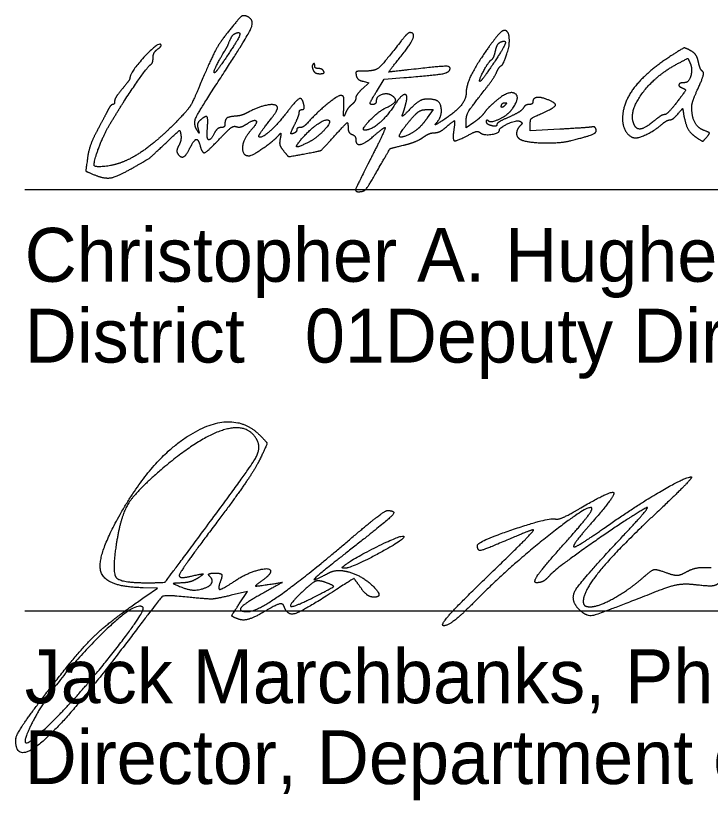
# Model space of a CAD drawing. Extents: x 0 to 64.8, y -5 to 22.
# Drawn here: x 24.504 to 26.31, y 6.793 to 8.831 of the extents above; entities that cross this region are included whole.
import ezdxf

# ---------------------------------------------------------------- set-up
doc = ezdxf.new("R2010")
doc.units = 0
doc.layers.add('SH_Data', color=7, linetype='Continuous')
doc.layers.add('SH_Text', color=7, linetype='Continuous')

msp = doc.modelspace()

# ---------------------------------------------------------------- linework, layer by layer
at = {"layer": 'SH_Data'}
for p, q in [((24.5279, 8.3799), (28.0279, 8.3799)), ((24.5279, 7.2848), (28.0279, 7.2848))]:
    msp.add_line(p, q, dxfattribs=at)
at = {"layer": 'SH_Text'}
for p, q in [((26.2707, 8.5169), (26.2707, 8.5169)), ((24.9902, 7.4899), (24.9902, 7.4899)), ((25.3555, 7.4), (25.3555, 7.4)), ((25.7273, 7.371), (25.7273, 7.371)), ((25.3107, 7.3583), (25.3107, 7.3583))]:
    msp.add_line(p, q, dxfattribs=at)
for points in [[(25.4419, 8.6333), (25.4621, 8.6661), (25.5135, 8.6703)], [(25.4072, 8.6608), (25.4226, 8.6571), (25.4054, 8.641)], [(25.5725, 8.5872), (25.5892, 8.5872), (25.574, 8.5655)], [(25.6948, 8.5538), (25.6749, 8.5396), (25.675, 8.5551)], [(25.9184, 8.5362), (25.8416, 8.5318), (25.8416, 8.548)], [(24.8425, 7.3229), (24.8732, 7.3441), (24.8354, 7.3448)], [(25.0855, 7.3031), (25.1067, 7.3354), (25.0649, 7.3253)]]:
    msp.add_lwpolyline(points, dxfattribs=at)
for points in [[(25.0246, 8.6505), (25.1054, 8.7743), (25.1264, 8.8214), (25.1044, 8.8298)], [(25.1044, 8.8298), (25.0968, 8.8327), (25.0867, 8.8266), (25.0767, 8.8135)], [(25.0767, 8.8135), (25.0455, 8.7767), (25.0161, 8.7299), (24.9843, 8.6531)], [(25.0757, 8.7854), (25.0908, 8.7913), (25.0811, 8.7664), (25.0503, 8.721)], [(25.5291, 8.7872), (25.5258, 8.7872), (25.5156, 8.7774), (25.5063, 8.7655)], [(25.5143, 8.7364), (25.534, 8.7612), (25.5416, 8.7872), (25.5291, 8.7872)], [(25.7797, 8.7917), (25.7739, 8.7953), (25.7594, 8.7834), (25.75, 8.7706)], [(25.7863, 8.7492), (25.7883, 8.7642), (25.7857, 8.788), (25.7797, 8.7917)], [(25.0574, 8.7583), (25.0637, 8.7729), (25.0702, 8.7833), (25.0757, 8.7854)], [(25.75, 8.7706), (25.7275, 8.7428), (25.6751, 8.6581), (25.675, 8.6289)], [(24.8816, 8.7561), (24.8747, 8.763), (24.8021, 8.6844), (24.8013, 8.6692)], [(24.8733, 8.7442), (24.8797, 8.7489), (24.8834, 8.7542), (24.8816, 8.7561)], [(25.0481, 8.74), (25.052, 8.7469), (25.0562, 8.7536), (25.0574, 8.7583)], [(25.5063, 8.7655), (25.4587, 8.7043), (25.4382, 8.6872), (25.4124, 8.6872)], [(25.7658, 8.7632), (25.781, 8.7691), (25.7712, 8.7442), (25.7404, 8.6988)], [(25.7515, 8.74), (25.7538, 8.7507), (25.7603, 8.7611), (25.7658, 8.7632)], [(25.7566, 8.6888), (25.761, 8.6989), (25.7732, 8.7043), (25.7863, 8.7492)], [(26.2583, 8.7405), (26.2441, 8.7481), (26.2388, 8.7468), (26.2103, 8.7285)], [(24.8616, 8.7218), (24.8616, 8.7295), (24.8669, 8.7395), (24.8733, 8.7442)], [(25.0211, 8.6827), (25.0163, 8.6827), (25.0437, 8.7345), (25.0481, 8.74)], [(25.5258, 8.6905), (25.4738, 8.6845), (25.4736, 8.6853), (25.5143, 8.7364)], [(25.741, 8.7168), (25.7444, 8.7189), (25.7492, 8.7294), (25.7515, 8.74)], [(26.2103, 8.7285), (26.1449, 8.6865), (26.0816, 8.6051), (26.0816, 8.5631)], [(26.2788, 8.7112), (26.2762, 8.7232), (26.2676, 8.7355), (26.2583, 8.7405)], [(24.8548, 8.7038), (24.8585, 8.7061), (24.8616, 8.7142), (24.8616, 8.7218)], [(25.0503, 8.721), (25.036, 8.7), (25.0229, 8.6827), (25.0211, 8.6827)], [(25.2775, 8.7052), (25.2752, 8.703), (25.2751, 8.6965), (25.2772, 8.6908)], [(25.2816, 8.7016), (25.2816, 8.7059), (25.2797, 8.7075), (25.2775, 8.7052)], [(25.7112, 8.6605), (25.7064, 8.6605), (25.7338, 8.7124), (25.741, 8.7168)], [(26.1106, 8.5508), (26.0984, 8.5825), (26.1671, 8.6761), (26.2249, 8.7066)], [(26.2249, 8.7066), (26.2511, 8.7204), (26.2517, 8.7204), (26.2574, 8.7078)], [(26.2574, 8.7078), (26.264, 8.693), (26.2541, 8.6572), (26.2433, 8.6572)], [(26.2897, 8.6864), (26.2862, 8.6887), (26.2813, 8.6998), (26.2788, 8.7112)], [(24.7484, 8.5475), (24.7777, 8.5971), (24.847, 8.6989), (24.8548, 8.7038)], [(25.2772, 8.6908), (25.2794, 8.6851), (25.2875, 8.6805), (25.2951, 8.6805)], [(25.2912, 8.6938), (25.2859, 8.6938), (25.2816, 8.6973), (25.2816, 8.7016)], [(25.3049, 8.6872), (25.3027, 8.6908), (25.2965, 8.6938), (25.2912, 8.6938)], [(25.2951, 8.6805), (25.3028, 8.6805), (25.3072, 8.6835), (25.3049, 8.6872)], [(25.4124, 8.6872), (25.3923, 8.6872), (25.3877, 8.6849), (25.3895, 8.6758)], [(25.5135, 8.6703), (25.5954, 8.6771), (25.6303, 8.6833), (25.6331, 8.6916)], [(25.6331, 8.6916), (25.6359, 8.7001), (25.6065, 8.6997), (25.5258, 8.6905)], [(25.7404, 8.6988), (25.7261, 8.6778), (25.713, 8.6605), (25.7112, 8.6605)], [(25.7251, 8.6405), (25.7381, 8.657), (25.7523, 8.6788), (25.7566, 8.6888)], [(26.2789, 8.6445), (26.289, 8.6667), (26.2935, 8.684), (26.2897, 8.6864)], [(24.8013, 8.6692), (24.8012, 8.6663), (24.7922, 8.6535), (24.7813, 8.6408)], [(25.3895, 8.6758), (25.3907, 8.6696), (25.3986, 8.6628), (25.4072, 8.6608)], [(24.9843, 8.6531), (24.9656, 8.608), (24.9515, 8.5859), (24.9232, 8.5568)], [(24.9753, 8.5348), (24.966, 8.5495), (24.98, 8.5822), (25.0246, 8.6505)], [(26.2433, 8.6572), (26.2303, 8.6572), (26.2261, 8.6476), (26.2373, 8.6433)], [(26.2616, 8.5946), (26.2616, 8.6013), (26.2694, 8.6238), (26.2789, 8.6445)], [(24.7813, 8.6408), (24.7705, 8.6281), (24.7616, 8.6138), (24.7616, 8.6091)], [(25.3495, 8.6238), (25.3413, 8.6238), (25.2862, 8.5785), (25.2625, 8.5522)], [(25.3572, 8.5938), (25.3579, 8.6148), (25.3556, 8.6238), (25.3495, 8.6238)], [(25.4054, 8.641), (25.396, 8.6321), (25.3883, 8.6212), (25.3883, 8.6168)], [(25.4317, 8.6005), (25.4243, 8.6005), (25.4268, 8.6088), (25.4419, 8.6333)], [(25.4812, 8.6241), (25.47, 8.631), (25.4416, 8.6212), (25.4416, 8.6104)], [(25.4658, 8.5914), (25.4882, 8.602), (25.4947, 8.6158), (25.4812, 8.6241)], [(25.519, 8.6045), (25.5247, 8.6271), (25.5065, 8.6256), (25.4912, 8.6022)], [(25.675, 8.6289), (25.6749, 8.6126), (25.6435, 8.5771), (25.6116, 8.5573)], [(25.675, 8.5551), (25.675, 8.5715), (25.6872, 8.5923), (25.7251, 8.6405)], [(25.7924, 8.5856), (25.8179, 8.6192), (25.787, 8.6385), (25.7531, 8.6101)], [(26.2373, 8.6433), (26.2464, 8.6398), (26.2442, 8.634), (26.2232, 8.6068)], [(24.7616, 8.6091), (24.7616, 8.6044), (24.7594, 8.6005), (24.7566, 8.6005)], [(25.2537, 8.5988), (25.2498, 8.619), (25.233, 8.6117), (25.2083, 8.5789)], [(25.3883, 8.6168), (25.3883, 8.6124), (25.3834, 8.6048), (25.3775, 8.5999)], [(25.4416, 8.6104), (25.4416, 8.605), (25.4371, 8.6005), (25.4317, 8.6005)], [(25.5105, 8.5761), (25.513, 8.5829), (25.5168, 8.5956), (25.519, 8.6045)], [(25.5927, 8.6127), (25.5709, 8.6169), (25.5466, 8.6068), (25.5261, 8.5851)], [(25.6004, 8.5556), (25.6131, 8.5711), (25.608, 8.6098), (25.5927, 8.6127)], [(25.7531, 8.6101), (25.7413, 8.6001), (25.7278, 8.5866), (25.7232, 8.5799)], [(25.7672, 8.5991), (25.7684, 8.6024), (25.7722, 8.6051), (25.7755, 8.6051)], [(25.7755, 8.6051), (25.7804, 8.6051), (25.7807, 8.604), (25.7766, 8.5991)], [(25.8483, 8.6065), (25.8483, 8.6032), (25.8439, 8.6005), (25.8386, 8.6005)], [(25.885, 8.6138), (25.8676, 8.6205), (25.8483, 8.6166), (25.8483, 8.6065)], [(25.8715, 8.5774), (25.9051, 8.5921), (25.9097, 8.6044), (25.885, 8.6138)], [(26.2232, 8.6068), (26.2095, 8.589), (26.1948, 8.5743), (26.1905, 8.5741)], [(24.744, 8.5855), (24.7399, 8.5772), (24.7272, 8.5533), (24.7159, 8.5322)], [(24.7566, 8.6005), (24.7539, 8.6004), (24.7482, 8.5937), (24.744, 8.5855)], [(25.1844, 8.5947), (25.1795, 8.6027), (25.1376, 8.5952), (25.1116, 8.5817)], [(25.161, 8.5539), (25.176, 8.5729), (25.1866, 8.5912), (25.1844, 8.5947)], [(25.2416, 8.5802), (25.2416, 8.584), (25.2448, 8.5872), (25.2488, 8.5872)], [(25.2488, 8.5872), (25.2527, 8.5872), (25.2549, 8.5924), (25.2537, 8.5988)], [(25.3614, 8.5774), (25.3576, 8.5679), (25.3564, 8.5727), (25.3572, 8.5938)], [(25.3775, 8.5999), (25.3716, 8.595), (25.3644, 8.5849), (25.3614, 8.5774)], [(25.4117, 8.5338), (25.4008, 8.5338), (25.4461, 8.582), (25.4658, 8.5914)], [(25.4912, 8.6022), (25.4699, 8.5696), (25.4283, 8.5338), (25.4117, 8.5338)], [(25.5261, 8.5851), (25.5138, 8.5722), (25.5077, 8.5687), (25.5105, 8.5761)], [(25.5453, 8.5766), (25.5511, 8.5824), (25.5634, 8.5872), (25.5725, 8.5872)], [(25.7325, 8.5586), (25.7386, 8.5524), (25.7821, 8.5721), (25.7924, 8.5856)], [(25.7682, 8.5931), (25.7664, 8.5931), (25.7659, 8.5958), (25.7672, 8.5991)], [(25.7766, 8.5991), (25.7739, 8.5958), (25.7701, 8.5931), (25.7682, 8.5931)], [(25.8236, 8.591), (25.8207, 8.5858), (25.804, 8.5754), (25.7866, 8.5679)], [(25.8386, 8.6005), (25.8333, 8.6005), (25.8265, 8.5962), (25.8236, 8.591)], [(26.225, 8.5755), (26.2375, 8.5901), (26.238, 8.5901), (26.2401, 8.5772)], [(26.2932, 8.5333), (26.2769, 8.5394), (26.2616, 8.5692), (26.2616, 8.5946)], [(25.0026, 8.5368), (25.0049, 8.5642), (24.999, 8.5722), (24.985, 8.5605)], [(25.0777, 8.5703), (25.059, 8.569), (25.0483, 8.5617), (25.0483, 8.5501)], [(25.1116, 8.5817), (25.1006, 8.5759), (25.0854, 8.5708), (25.0777, 8.5703)], [(25.2083, 8.5789), (25.1853, 8.5485), (25.1421, 8.5111), (25.1365, 8.5167)], [(25.2291, 8.5474), (25.236, 8.5616), (25.2416, 8.5763), (25.2416, 8.5802)], [(25.5016, 8.5188), (25.5016, 8.5235), (25.5309, 8.5622), (25.5453, 8.5766)], [(25.574, 8.5655), (25.5657, 8.5536), (25.5527, 8.5393), (25.5453, 8.5338)], [(25.7232, 8.5799), (25.7185, 8.5733), (25.7058, 8.5615), (25.6948, 8.5538)], [(25.7866, 8.5679), (25.7692, 8.5604), (25.7549, 8.5515), (25.7549, 8.548)], [(25.8416, 8.548), (25.8416, 8.5608), (25.8479, 8.567), (25.8715, 8.5774)], [(26.0816, 8.5631), (26.0816, 8.5431), (26.1017, 8.5138), (26.1154, 8.5138)], [(26.1905, 8.5741), (26.1862, 8.574), (26.1737, 8.5663), (26.1628, 8.5572)], [(26.2045, 8.5605), (26.2086, 8.5605), (26.2178, 8.5673), (26.225, 8.5755)], [(26.2401, 8.5772), (26.2445, 8.5512), (26.257, 8.5265), (26.2707, 8.5169)], [(24.7083, 8.4426), (24.7083, 8.4565), (24.7333, 8.5218), (24.7484, 8.5475)], [(24.9232, 8.5568), (24.88, 8.5126), (24.8079, 8.4596), (24.7756, 8.4484)], [(24.985, 8.5605), (24.9787, 8.5554), (24.9761, 8.5464), (24.9784, 8.5379)], [(25.0368, 8.5137), (25.0571, 8.5351), (25.0717, 8.5455), (25.0782, 8.5429)], [(25.0483, 8.5501), (25.0483, 8.5448), (25.0439, 8.5405), (25.0385, 8.5405)], [(25.0782, 8.5429), (25.0838, 8.5408), (25.0957, 8.5438), (25.1046, 8.5497)], [(25.1046, 8.5497), (25.1255, 8.5634), (25.1334, 8.5521), (25.116, 8.5334)], [(25.1365, 8.5167), (25.135, 8.5182), (25.1461, 8.535), (25.161, 8.5539)], [(25.2258, 8.5251), (25.219, 8.5225), (25.2199, 8.5283), (25.2291, 8.5474)], [(25.2625, 8.5522), (25.2567, 8.5458), (25.2481, 8.5405), (25.2435, 8.5405)], [(25.2456, 8.5087), (25.2686, 8.5357), (25.3124, 8.5653), (25.3192, 8.5585)], [(25.3192, 8.5585), (25.3244, 8.5533), (25.2874, 8.5137), (25.2678, 8.5036)], [(25.3332, 8.5187), (25.3628, 8.5513), (25.3682, 8.5549), (25.3682, 8.542)], [(25.3682, 8.542), (25.3682, 8.5336), (25.3728, 8.525), (25.3783, 8.5229)], [(25.6116, 8.5573), (25.5958, 8.5475), (25.5935, 8.5471), (25.6004, 8.5556)], [(25.6216, 8.5405), (25.6423, 8.5585), (25.6465, 8.5573), (25.6431, 8.5346)], [(25.7283, 8.5557), (25.7283, 8.5596), (25.7302, 8.5609), (25.7325, 8.5586)], [(25.7416, 8.5453), (25.7343, 8.5472), (25.7283, 8.5519), (25.7283, 8.5557)], [(25.7549, 8.548), (25.7549, 8.5446), (25.7489, 8.5433), (25.7416, 8.5453)], [(25.7616, 8.5334), (25.7616, 8.5411), (25.8087, 8.5611), (25.816, 8.5565)], [(25.8155, 8.5451), (25.8066, 8.5362), (25.806, 8.516), (25.8146, 8.5107)], [(25.816, 8.5565), (25.8205, 8.5537), (25.8204, 8.5499), (25.8155, 8.5451)], [(26.0025, 8.5422), (25.9985, 8.5413), (25.9606, 8.5386), (25.9184, 8.5362)], [(26.0127, 8.5364), (26.0112, 8.5405), (26.0066, 8.5431), (26.0025, 8.5422)], [(26.1628, 8.5572), (26.1405, 8.5384), (26.1165, 8.5354), (26.1106, 8.5508)], [(26.1154, 8.5138), (26.1263, 8.5138), (26.1662, 8.5338), (26.181, 8.5466)], [(26.181, 8.5466), (26.1898, 8.5543), (26.2004, 8.5605), (26.2045, 8.5605)], [(24.7159, 8.5322), (24.7047, 8.5112), (24.6934, 8.479), (24.691, 8.4606)], [(24.8973, 8.503), (24.9275, 8.5316), (24.9319, 8.5339), (24.9337, 8.5217)], [(24.9337, 8.5217), (24.9348, 8.5141), (24.9325, 8.5017), (24.9284, 8.4941)], [(24.9784, 8.5379), (24.9816, 8.5261), (24.9811, 8.5256), (24.9753, 8.5348)], [(25.0216, 8.5272), (25.0105, 8.5064), (25.0004, 8.5115), (25.0026, 8.5368)], [(25.0385, 8.5405), (25.0331, 8.5405), (25.0255, 8.5345), (25.0216, 8.5272)], [(25.116, 8.5334), (25.0957, 8.5116), (25.0924, 8.4672), (25.1111, 8.4672)], [(25.1111, 8.4672), (25.1196, 8.4672), (25.1798, 8.5099), (25.1905, 8.5235)], [(25.1905, 8.5235), (25.1936, 8.5274), (25.1943, 8.5228), (25.1922, 8.5129)], [(25.2349, 8.5346), (25.2349, 8.5313), (25.2308, 8.527), (25.2258, 8.5251)], [(25.2435, 8.5405), (25.2388, 8.5405), (25.2349, 8.5378), (25.2349, 8.5346)], [(25.3783, 8.5229), (25.3838, 8.5208), (25.3883, 8.5149), (25.3883, 8.5098)], [(25.4642, 8.5405), (25.4664, 8.5405), (25.4492, 8.503), (25.4258, 8.4572)], [(25.4373, 8.5205), (25.4498, 8.5315), (25.4619, 8.5405), (25.4642, 8.5405)], [(25.5453, 8.5338), (25.5304, 8.5228), (25.5016, 8.5129), (25.5016, 8.5188)], [(25.5626, 8.5148), (25.5724, 8.5216), (25.5862, 8.5272), (25.5933, 8.5272)], [(25.5933, 8.5272), (25.6004, 8.5272), (25.6132, 8.5332), (25.6216, 8.5405)], [(25.6431, 8.5346), (25.6393, 8.5085), (25.6496, 8.5043), (25.6792, 8.5201)], [(25.6792, 8.5201), (25.6959, 8.5291), (25.7066, 8.5313), (25.7119, 8.527)], [(25.7119, 8.527), (25.7201, 8.5201), (25.7616, 8.5255), (25.7616, 8.5334)], [(25.9483, 8.5068), (25.9949, 8.5187), (26.0157, 8.5283), (26.0127, 8.5364)], [(26.3015, 8.5171), (26.3083, 8.5253), (26.3069, 8.5281), (26.2932, 8.5333)], [(24.8141, 8.4389), (24.8528, 8.4614), (24.8555, 8.4635), (24.8973, 8.503)], [(24.9562, 8.485), (24.9673, 8.5077), (24.9789, 8.5116), (24.9835, 8.4941)], [(24.9835, 8.4941), (24.9891, 8.4728), (25.003, 8.4779), (25.0368, 8.5137)], [(25.1922, 8.5129), (25.1896, 8.5011), (25.1925, 8.4901), (25.2008, 8.4799)], [(25.2678, 8.5036), (25.24, 8.4892), (25.2308, 8.4914), (25.2456, 8.5087)], [(25.2558, 8.4724), (25.2953, 8.4796), (25.3007, 8.4829), (25.3332, 8.5187)], [(25.3883, 8.5098), (25.3883, 8.494), (25.4133, 8.4995), (25.4373, 8.5205)], [(25.5111, 8.4944), (25.5297, 8.4988), (25.5529, 8.508), (25.5626, 8.5148)], [(25.8146, 8.5107), (25.8285, 8.5021), (25.9196, 8.4994), (25.9483, 8.5068)], [(26.2707, 8.5169), (26.288, 8.5048), (26.2913, 8.5048), (26.3015, 8.5171)], [(24.9284, 8.4941), (24.9243, 8.4865), (24.9228, 8.4773), (24.925, 8.4737)], [(24.925, 8.4737), (24.9325, 8.4616), (24.9475, 8.4671), (24.9562, 8.485)], [(25.452, 8.4418), (25.4762, 8.4843), (25.4789, 8.4868), (25.5111, 8.4944)], [(24.691, 8.4606), (24.6866, 8.4277), (24.6869, 8.4271), (24.7083, 8.4181)], [(25.2008, 8.4799), (25.2128, 8.4651), (25.2148, 8.4648), (25.2558, 8.4724)], [(24.7756, 8.4484), (24.7553, 8.4413), (24.7083, 8.4373), (24.7083, 8.4426)], [(25.4258, 8.4572), (25.392, 8.3907), (25.3857, 8.3738), (25.3948, 8.3738)], [(25.3948, 8.3738), (25.4096, 8.3738), (25.421, 8.3874), (25.452, 8.4418)], [(24.7083, 8.4181), (24.7354, 8.4067), (24.7708, 8.4137), (24.8141, 8.4389)], [(24.7789, 7.5406), (24.8651, 7.691), (25.0732, 7.807), (25.1389, 7.7414)], [(25.1299, 7.7322), (25.104, 7.7742), (24.9779, 7.733), (24.8825, 7.6514)], [(24.9902, 7.4899), (25.1115, 7.6533), (25.144, 7.7095), (25.1299, 7.7322)], [(25.1389, 7.7414), (25.1577, 7.7226), (25.1577, 7.7175), (25.1394, 7.6791)], [(25.1394, 7.6791), (25.1284, 7.6561), (25.0767, 7.5806), (25.0245, 7.5112)], [(24.8825, 7.6514), (24.8159, 7.5944), (24.7771, 7.5303), (24.766, 7.459)], [(26.0326, 7.4991), (26.1131, 7.5557), (26.2445, 7.6329), (26.2602, 7.6329)], [(26.2602, 7.6329), (26.265, 7.6329), (26.2237, 7.5903), (26.1684, 7.5382)], [(25.9736, 7.5526), (26.0524, 7.5988), (26.0646, 7.5855), (26.0054, 7.5182)], [(25.369, 7.4671), (25.4194, 7.51), (25.4649, 7.5451), (25.4701, 7.5453)], [(25.4701, 7.5453), (25.495, 7.5458), (25.4716, 7.5202), (25.3857, 7.4529)], [(26.0017, 7.5524), (25.9921, 7.562), (25.7824, 7.395), (25.7045, 7.3158)], [(26.142, 7.5519), (26.0929, 7.5241), (25.9046, 7.3919), (25.8914, 7.376)], [(25.908, 7.5234), (25.9136, 7.5216), (25.9431, 7.5347), (25.9736, 7.5526)], [(25.9239, 7.452), (25.9702, 7.5037), (26.0052, 7.5489), (26.0017, 7.5524)], [(26.0768, 7.473), (26.123, 7.5222), (26.1523, 7.5577), (26.142, 7.5519)], [(24.8354, 7.3448), (24.7375, 7.3465), (24.7141, 7.4276), (24.7789, 7.5406)], [(25.7047, 7.4548), (25.7049, 7.4654), (25.8923, 7.5285), (25.908, 7.5234)], [(26.1684, 7.5382), (26.0687, 7.4445), (25.9795, 7.3364), (25.9795, 7.3094)], [(25.0245, 7.5112), (24.9722, 7.4419), (24.9295, 7.3812), (24.9295, 7.3764)], [(26.0054, 7.5182), (25.9774, 7.4864), (25.9545, 7.4567), (25.9545, 7.4523)], [(24.844, 7.3579), (24.8907, 7.3579), (24.8953, 7.3621), (24.9902, 7.4899)], [(25.7273, 7.371), (25.7983, 7.4394), (25.8537, 7.4954), (25.8502, 7.4954)], [(25.8502, 7.4954), (25.8468, 7.4954), (25.8178, 7.4842), (25.7857, 7.4704)], [(25.9545, 7.4523), (25.9545, 7.4478), (25.9896, 7.4689), (26.0326, 7.4991)], [(25.1076, 7.2829), (25.1307, 7.2829), (25.2567, 7.3717), (25.369, 7.4671)], [(25.3555, 7.4), (25.3759, 7.4179), (25.5079, 7.4836), (25.5131, 7.4785)], [(25.5131, 7.4785), (25.5193, 7.4723), (25.3767, 7.3954), (25.359, 7.3954)], [(25.7857, 7.4704), (25.7231, 7.4436), (25.7044, 7.44), (25.7047, 7.4548)], [(25.9697, 7.2874), (25.9445, 7.3126), (25.9734, 7.3627), (26.0768, 7.473)], [(24.766, 7.459), (24.7545, 7.3857), (24.776, 7.3579), (24.844, 7.3579)], [(25.3857, 7.4529), (25.2925, 7.3799), (25.271, 7.3584), (25.315, 7.3819)], [(25.8581, 7.3579), (25.8478, 7.3579), (25.8767, 7.3992), (25.9239, 7.452)], [(24.9638, 7.3757), (24.9894, 7.3816), (24.9934, 7.3804), (24.9795, 7.371)], [(25.0086, 7.3747), (25.004, 7.3792), (25.0103, 7.3829), (25.0225, 7.3829)], [(25.0225, 7.3829), (25.037, 7.3829), (25.0422, 7.3765), (25.0375, 7.3642)], [(25.0736, 7.3623), (25.1025, 7.3821), (25.167, 7.3996), (25.167, 7.3877)], [(25.167, 7.3877), (25.167, 7.3832), (25.1572, 7.3723), (25.1453, 7.3636)], [(25.315, 7.3819), (25.3276, 7.3886), (25.3515, 7.3907), (25.3681, 7.3865)], [(25.359, 7.3954), (25.3542, 7.3954), (25.3526, 7.3975), (25.3555, 7.4)], [(25.3681, 7.3865), (25.4042, 7.3774), (25.4625, 7.3204), (25.4358, 7.3204)], [(26.137, 7.373), (26.1573, 7.391), (26.1701, 7.3936), (26.1939, 7.3846)], [(26.1939, 7.3846), (26.2141, 7.3769), (26.2329, 7.3776), (26.2489, 7.3867)], [(26.2489, 7.3867), (26.2623, 7.3942), (26.2906, 7.3989), (26.3119, 7.3971)], [(24.9295, 7.3764), (24.9295, 7.3716), (24.9449, 7.3713), (24.9638, 7.3757)], [(24.9795, 7.371), (24.9692, 7.364), (24.9495, 7.3579), (24.9357, 7.3573)], [(24.9399, 7.3447), (24.9698, 7.3327), (25.026, 7.3573), (25.0086, 7.3747)], [(25.0375, 7.3642), (25.0285, 7.3409), (25.0414, 7.3403), (25.0736, 7.3623)], [(25.1453, 7.3636), (25.1264, 7.3498), (25.1284, 7.3485), (25.161, 7.3534)], [(25.3107, 7.3583), (25.2935, 7.3647), (25.277, 7.3596), (25.2576, 7.3418)], [(25.4011, 7.3451), (25.3843, 7.3692), (25.3822, 7.3687), (25.3165, 7.3264)], [(25.617, 7.2461), (25.6067, 7.2463), (25.6563, 7.3025), (25.7273, 7.371)], [(25.8914, 7.376), (25.8831, 7.366), (25.8682, 7.3579), (25.8581, 7.3579)], [(25.9975, 7.2954), (26.0192, 7.2954), (26.1006, 7.3407), (26.137, 7.373)], [(26.3444, 7.3664), (26.3287, 7.3522), (26.3075, 7.3478), (26.2749, 7.352)], [(24.9357, 7.3573), (24.9133, 7.3565), (24.9138, 7.3551), (24.9399, 7.3447)], [(25.161, 7.3534), (25.1977, 7.359), (25.1976, 7.3587), (25.1522, 7.3336)], [(25.2576, 7.3418), (25.2133, 7.3013), (25.2246, 7.2924), (25.2826, 7.322)], [(25.2826, 7.322), (25.329, 7.3457), (25.3325, 7.3503), (25.3107, 7.3583)], [(25.4358, 7.3204), (25.4262, 7.3204), (25.4106, 7.3315), (25.4011, 7.3451)], [(26.2749, 7.352), (26.2457, 7.3557), (26.2058, 7.3493), (26.1693, 7.3348)], [(24.5916, 7.0807), (24.6692, 7.1812), (24.7493, 7.2585), (24.8425, 7.3229)], [(24.9237, 7.323), (24.8903, 7.3263), (24.8786, 7.3158), (24.8019, 7.2142)], [(25.0649, 7.3253), (25.0246, 7.3156), (25.0023, 7.3152), (24.9237, 7.323)], [(25.1522, 7.3336), (25.1011, 7.3054), (25.0814, 7.2829), (25.1076, 7.2829)], [(25.3165, 7.3264), (25.2476, 7.282), (25.2101, 7.2723), (25.202, 7.2966)], [(26.1693, 7.3348), (26.0233, 7.2772), (25.9882, 7.2688), (25.9697, 7.2874)], [(25.0843, 7.263), (25.0661, 7.27), (25.0662, 7.2736), (25.0855, 7.3031)], [(25.202, 7.2966), (25.1991, 7.3052), (25.1799, 7.3), (25.1508, 7.2828)], [(25.7045, 7.3158), (25.6667, 7.2773), (25.6273, 7.246), (25.617, 7.2461)], [(25.9795, 7.3094), (25.9795, 7.3017), (25.9876, 7.2954), (25.9975, 7.2954)], [(24.8354, 7.2937), (24.8145, 7.3146), (24.596, 7.0889), (24.5497, 6.9986)], [(24.6198, 7.0173), (24.6874, 7.0864), (24.8431, 7.286), (24.8354, 7.2937)], [(25.1508, 7.2828), (25.1252, 7.2677), (25.0953, 7.2588), (25.0843, 7.263)], [(24.8019, 7.2142), (24.6496, 7.0121), (24.5045, 6.8835), (24.5045, 6.9505)], [(24.5045, 6.9505), (24.5045, 6.9601), (24.5437, 7.0187), (24.5916, 7.0807)], [(24.5497, 6.9986), (24.5184, 6.9376), (24.55, 6.9461), (24.6198, 7.0173)]]:
    msp.add_open_spline(points, degree=2, dxfattribs=at)

# ---------------------------------------------------------------- texts
for s, p in [('Christopher A. Hughes, P.E.', (24.5279, 8.1399)), ('District       Deputy Director', (24.5279, 7.9299)), ('              01', (24.5279, 7.9299)), ('Jack Marchbanks, PhD', (24.5279, 7.0448)), ('Director, Department of Transportation', (24.5279, 6.8348))]:
    msp.add_text(s, height=0.14, dxfattribs=at).set_placement(p)

doc.saveas('drawing.dxf')
